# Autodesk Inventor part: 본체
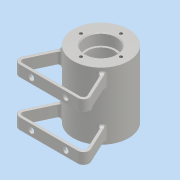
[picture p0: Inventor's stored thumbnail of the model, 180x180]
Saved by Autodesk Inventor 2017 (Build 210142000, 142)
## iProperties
Part Number: 본체
Material: 알루미늄 6061
Document SubType Name: Modeling
Designer: user
Density: 2.7 g/cm^3
Appearance: 알루미늄 - 평지
Mass: 310.254 g
Surface Area: 354.969 cm^2
Volume: 114.909 cm^3
Author: user
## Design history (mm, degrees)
sketch "스케치1"
  geometry: L1 (21, 0)-(21, -21); L2 (21, -21)-(14, -21); L3 (14, -21)-(14, -23); L4 (14, -23)-(16, -23); L5 (16, -23)-(16, -35); L6 (16, -35)-(29, -35); L7 (29, -35)-(29, 0); L8 (29, 0)-(21, 0); L9 (0, 0)-(0, -35); 1 further point
  constraints: 18 end point, 7 perpendicular, 2 vertical, 1 horizontal alignment, 1 midpoint
  dimensions: "d0" = 35 distance of L9.start L9.end; "d1" = 35 distance of L6.end L7.end; "d2" = 42 diameter of L1 L9; "d3" = 58 diameter of L7 L9; "d4" = 21 distance of L1.start L1.end; "d5" = 32 diameter of L5 L9; "d6" = 28 diameter of L3 L9; "d7" = 12 distance of L4.end L5.end
revolve "회전1" sketch "스케치1" stored, may be unused: angle "d8" = 90 deg
node "작업 평면1"
sketch "스케치2"
  geometry: L1 (-40, -55)-(40, -55); L2 (-40, -55)-(-22.743, -17.993); L3 (40, -55)-(22.743, -17.993); A1 r 29 centre (0, 0) between (-22.743, -17.993) and (22.743, -17.993) reference; 2 further points
  constraints: 6 end point, 2 point on circle, 1 horizontal, 1 midpoint, 1 vertical alignment
  dimensions: "d10" = 80 distance of L1.start L1.end; "d11" = 55 distance of point (0, -55) point (0, 0); "d12" = 65 deg angle of L1 L2; "d13" = 65 deg angle of L1 L3
extrude "돌출1" join sketch "스케치2" distance "d14" = 12; taper "d15" = 0 deg
sketch "스케치3"
  geometry: L1 (-35.291, -52)-(35.291, -52); L2 (35.291, -52)-(20.574, -20.438); L3 (-35.291, -52)-(-20.574, -20.438); L4 (-40, -55)-(40, -55) reference; L5 (-22.743, -17.993)-(-40, -55) reference; L6 (40, -55)-(22.743, -17.993) reference; A1 r 29 centre (0, 0) between (20.574, -20.438) and (-20.574, -20.438) reference; 2 further points
  constraints: 6 end point, 2 parallel, 2 point on circle, 1 horizontal, 2 other
  dimensions: "d16" = 3 distance between parallel lines of L4 L1; "d18" = 3 distance between parallel lines of L3 L5; "d19" = 3 distance between parallel lines of L6 L2
extrude "돌출2" cut sketch "스케치3" distance "d20" = 12; taper "d21" = 0 deg
node "작업 평면2"
sketch "스케치4"
  geometry: L1 (-29, 35)-(29, 35) reference; C1 r 5 at (0, 0); 1 further point
  constraints: 1 centre point, 1 coincident
  dimensions: "d23" = 10 diameter of C1; "d24" = 35 distance from line of C1.centre L1
extrude "돌출3" join sketch "스케치4" stored distance "d25" = 12; taper "d26" = 0 deg
hole "구멍1" diameter "d29" = 5.188; stored, may be unused: countersink angle "d33" = 90 deg, drill point angle "d35" = 118 deg; dims "d27" = 10, "d28" = 10, "d30" = 6, "d31" = 4, "d32" = 2, "d34" = 8
sketch "스케치5"
  geometry: C1 r 1.5 at (0, 0); 1 further point
  constraints: 1 centre point, 1 coincident
  dimensions: "d36" = 3 diameter of C1
extrude "돌출4" cut sketch "스케치5" distance "d37" = 25; taper "d38" = 0 deg
sketch "스케치6"
  geometry: 2 further points
  constraints: 1 vertical alignment
  dimensions: "d39" = 21 distance of point (0, 0) point (0, 21)
hole "구멍2" sketch "스케치6" at (0, 21) diameter "d40" = 3.242; stored, may be unused: countersink angle "d44" = 90 deg, drill point angle "d46" = 118 deg; dims "d41" = 8, "d42" = 4, "d43" = 2, "d45" = 10
sketch "스케치7"
  geometry: L1 (0, 12)-(80, 12) reference; C1 r 3 at (58, 6); C2 r 3 at (22, 6); 1 further point
  constraints: 2 centre point, 1 horizontal alignment
  dimensions: "d50" = 6 diameter of C1; "d51" = 6 diameter of C2; "d52" = 36 distance of C2.centre C1.centre; "d53" = 18 horizontal distance of C1.centre point (40, -18); "d54" = 6 distance from line of L1 C1.centre
extrude "돌출5" cut sketch "스케치7" distance "d55" = 5; taper "d56" = 0 deg
sketch "스케치8"
  geometry: L1 (0, 0)-(10.945, -30.07); L2 (0, 0)-(0, -29)
  constraints: 4 end point, 1 vertical, 1 vertical alignment, 1 other
  dimensions: "d57" = 20 deg angle of L1 L2; "d58" = 32 distance of L1.start L1.end
node "작업 평면3"
sketch "스케치9"
  geometry: C1 r 6 at (0, 0); 1 further point
  constraints: 1 centre point, 1 coincident
  dimensions: "d59" = 12 diameter of C1
extrude "돌출6" join sketch "스케치9" stored distance "d60" = 5; taper "d61" = 0 deg
sketch "스케치10"
  geometry: 2 further points
  constraints: 1 coincident
hole "구멍3" sketch "스케치10" at (0, 0) diameter "d62" = 5.188; stored, may be unused: countersink angle "d66" = 90 deg, drill point angle "d68" = 0 deg; dims "d63" = 12, "d64" = 4, "d65" = 2, "d67" = 20
fillet "모깎기1" dims "d69" = 6
fillet "모깎기2" dims "d70" = 3
fillet "모깎기3" dims "d71" = 0.5
fillet "모깎기4" dims "d72" = 1
fillet "모깎기5" dims "d73" = 3
node "작업 평면4"
sketch "스케치11"
  geometry: L1 (-29, -35)-(29, -35) reference; L2 (-29, 35)-(-29, -35) reference; 2 further points
  constraints: 1 other
  dimensions: "d75" = 35 distance from line of point (0, 0) L1; "d76" = 29 distance from line of point (0, 0) L2
feature "엠보싱1" sketch "스케치11" dims "d0" = 35, "d1" = 35, "d2" = 42, "d3" = 58, "d4" = 21, "d5" = 32, "d6" = 28, "d7" = 12, "d10" = 80, "d11" = 55, "d12" = 65 deg, "d13" = 65 deg, "d77" = 0.5, "d78" = 0
fillet "모깎기6" dims "d79" = 0.3
fillet "모깎기7" dims "d80" = 3
chamfer "모따기1" distance "d81" = 1; stored, may be unused: second distance "d82" = 2, angle "d83" = 45 deg
node "솔리드1"
mirror "미러1"
mirror "미러2"
pattern_circular "원형 패턴1" dims angle "d48" = 360 deg
mirror "미러3"
mirror "미러4"
other parameters: "d9" = 18, "d22" = 32, "d74" = -29
